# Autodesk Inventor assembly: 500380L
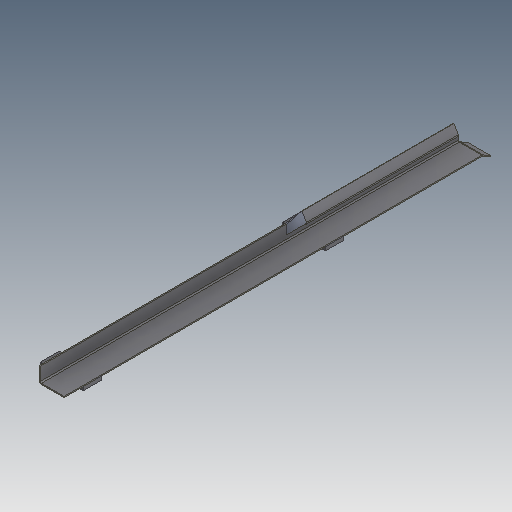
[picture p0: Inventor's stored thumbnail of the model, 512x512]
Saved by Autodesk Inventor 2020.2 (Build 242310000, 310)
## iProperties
Created: 2000-01
Part Number: 500380L
Description: WMT-CP,SS,XX,GUIDE,ANGLE
Document SubType Name: Assembly
Designer: sspink
Mass: 1184.99 g
Surface Area: 2689.76 cm^2
Volume: 450.261 cm^3
Density: 2.6318 g/cm^3
Control State: 0
Checked Out: False
Master: False
Shininess: 0.0
Length Units: 11269
Angle Units: 11279
Time Units: 11290
Mass Units: 11283
Length Display Precision: 3
Angle Display Precision: 2
Compacted: True
Dimensions: 53,1x1139,7x114 mm
Mass: 1,185 kg
DocNumber: 500380L.iam
Folder: .
VDS_Category: 3D Komponenten
Density: 0.0
Volumn: 0.0
Area: 0.0
PropertySet Name: Model Information
Author: sspink
Revision Number: -
Title: 500380L
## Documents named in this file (4)
- D:\07 - DEMODATEN\OTX 2019 - Dataset - UPDATE - Dez2019\Designs\07-Packing machine\500380L.iam
- D:\07 - DEMODATEN\OTX 2019 - Dataset - UPDATE - Dez2019\Designs\07-Packing machine\Parts\ADSK-011359.ipt
- D:\07 - DEMODATEN\OTX 2019 - Dataset - UPDATE - Dez2019\Designs\07-Packing machine\Parts\ADSK-011363.ipt
- D:\07 - DEMODATEN\OTX 2019 - Dataset - UPDATE - Dez2019\Designs\07-Packing machine\Parts\ADSK-011381.ipt
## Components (4 placed, 3 different names)
1. ADSK-011359:1 — Passend:6, Fluchtend:7, Passend:7, Passend:8, Fluchtend:8, Passend:9, Passend:10, Passend:11
2. ADSK-011363:3 — Passend:6, Fluchtend:7, Passend:7, Fluchtend:9
3. ADSK-011363:4 — Passend:8, Fluchtend:8, Fluchtend:9
4. ADSK-011381:2 — Passend:9, Passend:10, Passend:11
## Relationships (9: Mate 6, Flush 3)
- Passend:6 [Mate]: ADSK-011359:1 ↔ ADSK-011363:3
- Fluchtend:7 [Flush]: ADSK-011359:1 ↔ ADSK-011363:3
- Passend:7 [Mate]: ADSK-011359:1 ↔ ADSK-011363:3
- Passend:8 [Mate]: ADSK-011359:1 ↔ ADSK-011363:4
- Fluchtend:8 [Flush]: ADSK-011359:1 ↔ ADSK-011363:4
- Fluchtend:9 [Flush]: ADSK-011363:3 ↔ ADSK-011363:4
- Passend:9 [Mate]: ADSK-011359:1 ↔ ADSK-011381:2
- Passend:10 [Mate]: ADSK-011359:1 ↔ ADSK-011381:2
- Passend:11 [Mate]: ADSK-011359:1 ↔ ADSK-011381:2
